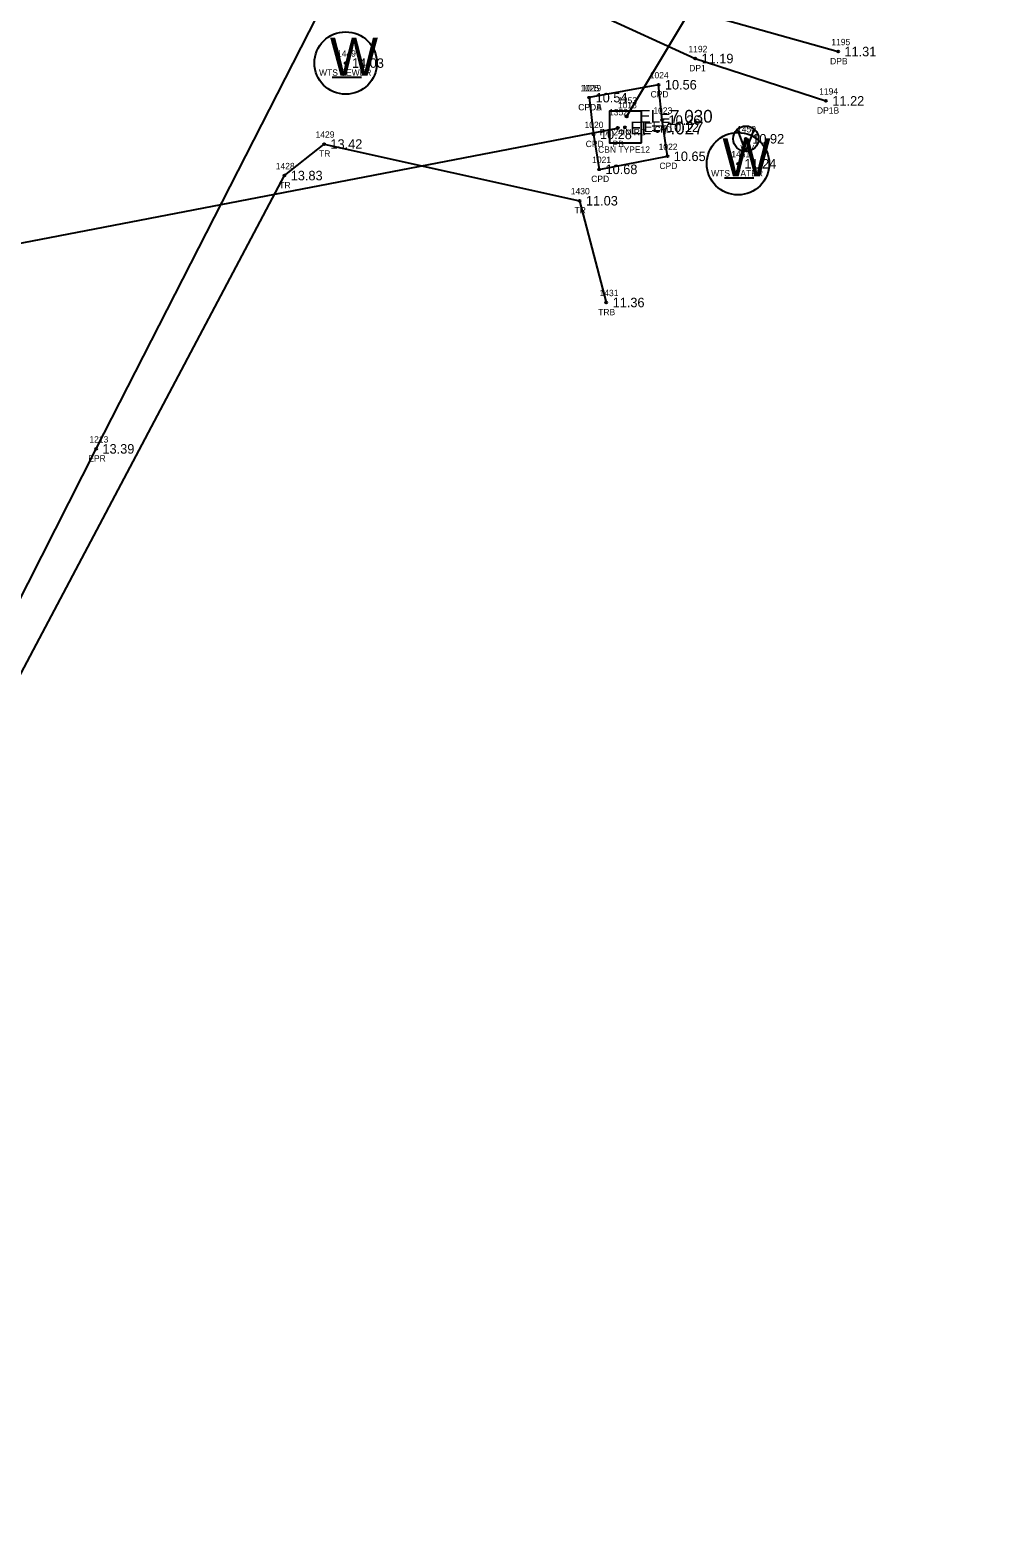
# Model space of a CAD drawing. Extents: x 2072307 to 2072993, y 127574 to 129736.
# Drawn here: x 2072830.3 to 2072979.9, y 128354.3 to 128591.5 of the extents above; entities that cross this region are included whole.
import ezdxf

# ---------------------------------------------------------------- set-up
doc = ezdxf.new("R2010")
doc.units = 0
for name, color, linetype in [('RD_EX_Conc', 7, 'Continuous'), ('RD_EX_Conc_txCode', 7, 'Continuous'), ('RD_EX_DR_Inlet', 7, 'Continuous'), ('RD_EX_DR_Inlet_txCode', 7, 'Continuous'), ('RD_EX_DR_Pipe', 7, 'Continuous'), ('RD_EX_DR_Pipe_txCode', 7, 'Continuous'), ('RD_EX_Driveway', 7, 'Continuous'), ('RD_EX_Driveway_txCode', 7, 'Continuous'), ('RD_EX_Road', 7, 'Continuous'), ('RD_EX_Road_txCode', 7, 'Continuous'), ('RD_EX_TX_Conc_ELEV', 7, 'Continuous'), ('RD_EX_TX_DR_Inlet_ELEV', 7, 'Continuous'), ('RD_EX_TX_Driveway_ELEV', 7, 'Continuous'), ('RD_EX_TX_Road_ELEV', 7, 'Continuous'), ('RD_EX_TX_UT_ELEV', 7, 'Continuous'), ('RD_EX_TX_VEG_ELEV', 7, 'Continuous'), ('RD_EX_UT', 7, 'Continuous'), ('RD_EX_UT_txCode', 7, 'Continuous'), ('RD_EX_VEG', 7, 'Continuous'), ('RD_EX_VEG_txCode', 7, 'Continuous'), ('RD_SMD_Locator', 7, 'Continuous'), ('RD_TX_Pipe_ElevEX', 7, 'Continuous')]:
    doc.layers.add(name, color=color, linetype=linetype)

msp = doc.modelspace()

# ---------------------------------------------------------------- linework, layer by layer
at = {"layer": 'RD_EX_Conc'}
msp.add_lwpolyline([(2072918.29, 128580.9), (2072918.98, 128575.12), (2072919.85, 128569.62), (2072930.59, 128571.67), (2072929.77, 128577.37), (2072929.19, 128582.93), (2072918.29, 128580.9)], dxfattribs=at)
at = {"layer": 'RD_EX_DR_Inlet'}
msp.add_line((2072926.5, 128573.78), (2072926.5, 128578.78), dxfattribs=at)
msp.add_lwpolyline([(2072926.5, 128573.78), (2072926.5, 128578.78), (2072921.5, 128578.78), (2072921.5, 128573.78)], close=True, dxfattribs=at)
at = {"layer": 'RD_EX_DR_Pipe'}
for p, q in [((2072924.18, 128577.97), (2072979.91, 128670.87)), ((2072793.14, 128551.15), (2072922.75, 128576.12))]:
    msp.add_line(p, q, dxfattribs=at)
at = {"layer": 'RD_EX_Driveway'}
for points in [[(2072899.84, 128627.36), (2072909.96, 128615.58), (2072924.58, 128600.62), (2072937.42, 128593.78), (2072957.44, 128588.15)], [(2072893.24, 128622.62), (2072904.64, 128610.03), (2072919.61, 128594.09), (2072934.96, 128587.05), (2072955.54, 128580.39)]]:
    msp.add_lwpolyline(points, dxfattribs=at)
at = {"layer": 'RD_EX_Road'}
msp.add_lwpolyline([(2072789.45, 128345.69), (2072789.46, 128382.93), (2072788.01, 128408.09), (2072794.06, 128431.26), (2072804.3, 128453.88), (2072840.7, 128525.64), (2072876.68, 128596.08), (2072888.72, 128617.36), (2072893.24, 128622.62), (2072899.84, 128627.36), (2072910.72, 128631.76), (2072918.79, 128632.23), (2072935.82, 128627.02), (2072957.37, 128619.98)], dxfattribs=at)
at = {"layer": 'RD_EX_UT'}
for p, q in [((2072877.83, 128584.14), (2072882.46, 128584.14)), ((2072942.94, 128572.43), (2072941.63, 128575.92)), ((2072942.94, 128572.43), (2072944.26, 128575.88)), ((2072939.57, 128568.3), (2072944.2, 128568.3))]:
    msp.add_line(p, q, dxfattribs=at)
for centre, radius in [((2072879.96, 128586.34), 4.91), ((2072942.94, 128574.43), 2), ((2072941.7, 128570.5), 4.91)]:
    msp.add_circle(centre, radius, dxfattribs=at)
at = {"layer": 'RD_EX_VEG'}
msp.add_lwpolyline([(2072791.29, 128345.62), (2072800.72, 128429.53), (2072808.9, 128452.58), (2072870.32, 128568.64), (2072876.57, 128573.6), (2072916.77, 128564.68), (2072920.97, 128548.67)], dxfattribs=at)
at = {"layer": 'RD_SMD_Locator'}
for centre, radius in [((2072957.44, 128588.15), 0.15), ((2072879.96, 128586.34), 0.15), ((2072934.96, 128587.05), 0.15), ((2072929.19, 128582.93), 0.15), ((2072918.29, 128580.9), 0.15), ((2072918.29, 128580.9), 0.15), ((2072955.54, 128580.39), 0.15), ((2072924.18, 128577.97), 0.2), ((2072922.75, 128576.12), 0.2), ((2072923.91, 128576.23), 0.15), ((2072929.77, 128577.37), 0.15), ((2072876.57, 128573.6), 0.15), ((2072918.98, 128575.12), 0.15), ((2072942.94, 128574.43), 0.15), ((2072930.59, 128571.67), 0.15), ((2072870.32, 128568.64), 0.15), ((2072919.85, 128569.62), 0.15), ((2072941.7, 128570.5), 0.15), ((2072916.77, 128564.68), 0.15), ((2072920.97, 128548.67), 0.15), ((2072840.7, 128525.64), 0.15)]:
    msp.add_circle(centre, radius, dxfattribs=at)

# ---------------------------------------------------------------- texts
at = {"layer": 'RD_EX_Conc_txCode'}
for s, p in [('1025', (2072916.9, 128581.9)), ('1019', (2072917.19, 128581.9)), ('1024', (2072927.81, 128583.93)), ('CPD', (2072927.94, 128580.93)), ('CPDA', (2072916.55, 128578.9)), ('CPDB', (2072916.57, 128578.9)), ('1023', (2072928.38, 128578.37)), ('1020', (2072917.55, 128576.12)), ('CPD', (2072928.52, 128575.37)), ('CPD', (2072917.73, 128573.12)), ('1022', (2072929.21, 128572.67)), ('1021', (2072918.75, 128570.62)), ('CPD', (2072918.6, 128567.62)), ('CPD', (2072929.34, 128569.67))]:
    msp.add_text(s, height=1, dxfattribs=at).set_placement(p)
at = {"layer": 'RD_EX_DR_Inlet_txCode'}
for s, p in [('1018', (2072922.8, 128579.23)), ('CBN TYPE12', (2072919.68, 128572.23))]:
    msp.add_text(s, height=1, dxfattribs=at).set_placement(p)
at = {"layer": 'RD_EX_DR_Pipe_txCode'}
for s, p in [('1353', (2072922.83, 128579.97)), ('1352', (2072921.41, 128578.12)), ('PA 24IN RC', (2072919.94, 128574.97)), ('PB', (2072921.97, 128573.12))]:
    msp.add_text(s, height=1, dxfattribs=at).set_placement(p)
at = {"layer": 'RD_EX_Driveway_txCode'}
for s, p in [('1195', (2072956.38, 128589.15)), ('1192', (2072933.9, 128588.05)), ('DP1', (2072934.02, 128585.05)), ('DPB', (2072956.19, 128586.15)), ('1194', (2072954.47, 128581.39)), ('DP1B', (2072954.12, 128578.39))]:
    msp.add_text(s, height=1, dxfattribs=at).set_placement(p)
at = {"layer": 'RD_EX_Road_txCode'}
for s, p in [('1213', (2072839.64, 128526.64)), ('EPR', (2072839.47, 128523.64))]:
    msp.add_text(s, height=1, dxfattribs=at).set_placement(p)
at = {"layer": 'RD_EX_TX_Conc_ELEV'}
for s, p in [('10.56', (2072930.19, 128582.18)), ('10.54', (2072919.29, 128580.15)), ('10.54', (2072919.29, 128580.15)), ('10.26', (2072930.77, 128576.62)), ('10.28', (2072919.98, 128574.37)), ('10.65', (2072931.59, 128570.92)), ('10.68', (2072920.85, 128568.87))]:
    msp.add_text(s, height=1.5, dxfattribs=at).set_placement(p)
at = {"layer": 'RD_EX_TX_DR_Inlet_ELEV'}
msp.add_text('EL=10.12', height=1.5, dxfattribs=at).set_placement((2072926.91, 128575.48))
at = {"layer": 'RD_EX_TX_Driveway_ELEV'}
for s, p in [('11.19', (2072935.96, 128586.3)), ('11.31', (2072958.44, 128587.4)), ('11.22', (2072956.54, 128579.64))]:
    msp.add_text(s, height=1.5, dxfattribs=at).set_placement(p)
at = {"layer": 'RD_EX_TX_Road_ELEV'}
msp.add_text('13.39', height=1.5, dxfattribs=at).set_placement((2072841.7, 128524.89))
at = {"layer": 'RD_EX_TX_UT_ELEV'}
for s, p in [('14.03', (2072880.96, 128585.59)), ('10.92', (2072943.94, 128573.68)), ('11.24', (2072942.7, 128569.75))]:
    msp.add_text(s, height=1.5, dxfattribs=at).set_placement(p)
at = {"layer": 'RD_EX_TX_VEG_ELEV'}
for s, p in [('13.42', (2072877.57, 128572.85)), ('13.83', (2072871.32, 128567.89)), ('11.03', (2072917.77, 128563.93)), ('11.36', (2072921.97, 128547.92))]:
    msp.add_text(s, height=1.5, dxfattribs=at).set_placement(p)
at = {"layer": 'RD_EX_UT'}
for p in [(2072877.49, 128584.34), (2072939.24, 128568.5)]:
    msp.add_text('W', height=6, dxfattribs=at).set_placement(p)
at = {"layer": 'RD_EX_UT_txCode'}
for s, p in [('1449', (2072878.61, 128587.34)), ('WTS SEWER', (2072875.78, 128584.34)), ('1450', (2072941.55, 128575.43)), ('WV', (2072942.08, 128572.43)), ('1451', (2072940.64, 128571.5)), ('WTS WATER', (2072937.47, 128568.5))]:
    msp.add_text(s, height=1, dxfattribs=at).set_placement(p)
at = {"layer": 'RD_EX_VEG_txCode'}
for s, p in [('1429', (2072875.23, 128574.6)), ('TR', (2072875.78, 128571.6)), ('1428', (2072868.97, 128569.64)), ('TR', (2072869.52, 128566.64)), ('1430', (2072915.39, 128565.68)), ('TR', (2072915.98, 128562.68)), ('1431', (2072919.91, 128549.67)), ('TRB', (2072919.7, 128546.67))]:
    msp.add_text(s, height=1, dxfattribs=at).set_placement(p)
at = {"layer": 'RD_TX_Pipe_ElevEX'}
for s, p in [('EL=7.030', (2072926.18, 128576.97)), ('EL=7.027', (2072924.75, 128575.12))]:
    msp.add_text(s, height=2, dxfattribs=at).set_placement(p)

doc.saveas('drawing.dxf')
